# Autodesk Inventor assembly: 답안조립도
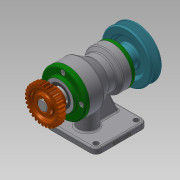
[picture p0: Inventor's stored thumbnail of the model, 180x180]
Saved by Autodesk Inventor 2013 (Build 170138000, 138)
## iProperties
Created: 2019-01
Part Number: 답안조립도
Document SubType Name: Assembly
Designer: Administrator
Author: Administrator
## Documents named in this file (15)
- C:\Users\Administrator\Desktop\490107V1029\답안조립도.iam
- C:\Users\Administrator\Desktop\490107V1029\본체.ipt
- C:\Users\Administrator\Desktop\490107V1029\V-벨트풀리.ipt
- C:\Users\Administrator\Desktop\490107V1029\뒤커버.ipt
- C:\Users\Administrator\Desktop\490107V1029\멈춤나사 M3.ipt
- C:\Users\Administrator\Desktop\490107V1029\베어링 6203.ipt
- C:\Users\Administrator\Desktop\490107V1029\베어링 6205.ipt
- C:\Users\Administrator\Desktop\490107V1029\볼트 M4.ipt
- C:\Users\Administrator\Desktop\490107V1029\스퍼기어.ipt
- C:\Users\Administrator\Desktop\490107V1029\앞커버.ipt
- C:\Users\Administrator\Desktop\490107V1029\오일 실 17 30 8.ipt
- C:\Users\Administrator\Desktop\490107V1029\오일 실 25 38 8.ipt
- C:\Users\Administrator\Desktop\490107V1029\축.ipt
- C:\Users\Administrator\Desktop\490107V1029\키 5 x 5 x 20.ipt
- C:\Users\Administrator\Desktop\490107V1029\키 6 x 6 x 18.ipt
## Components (1 placed, 1 different names)
1. V-벨트풀리:1
